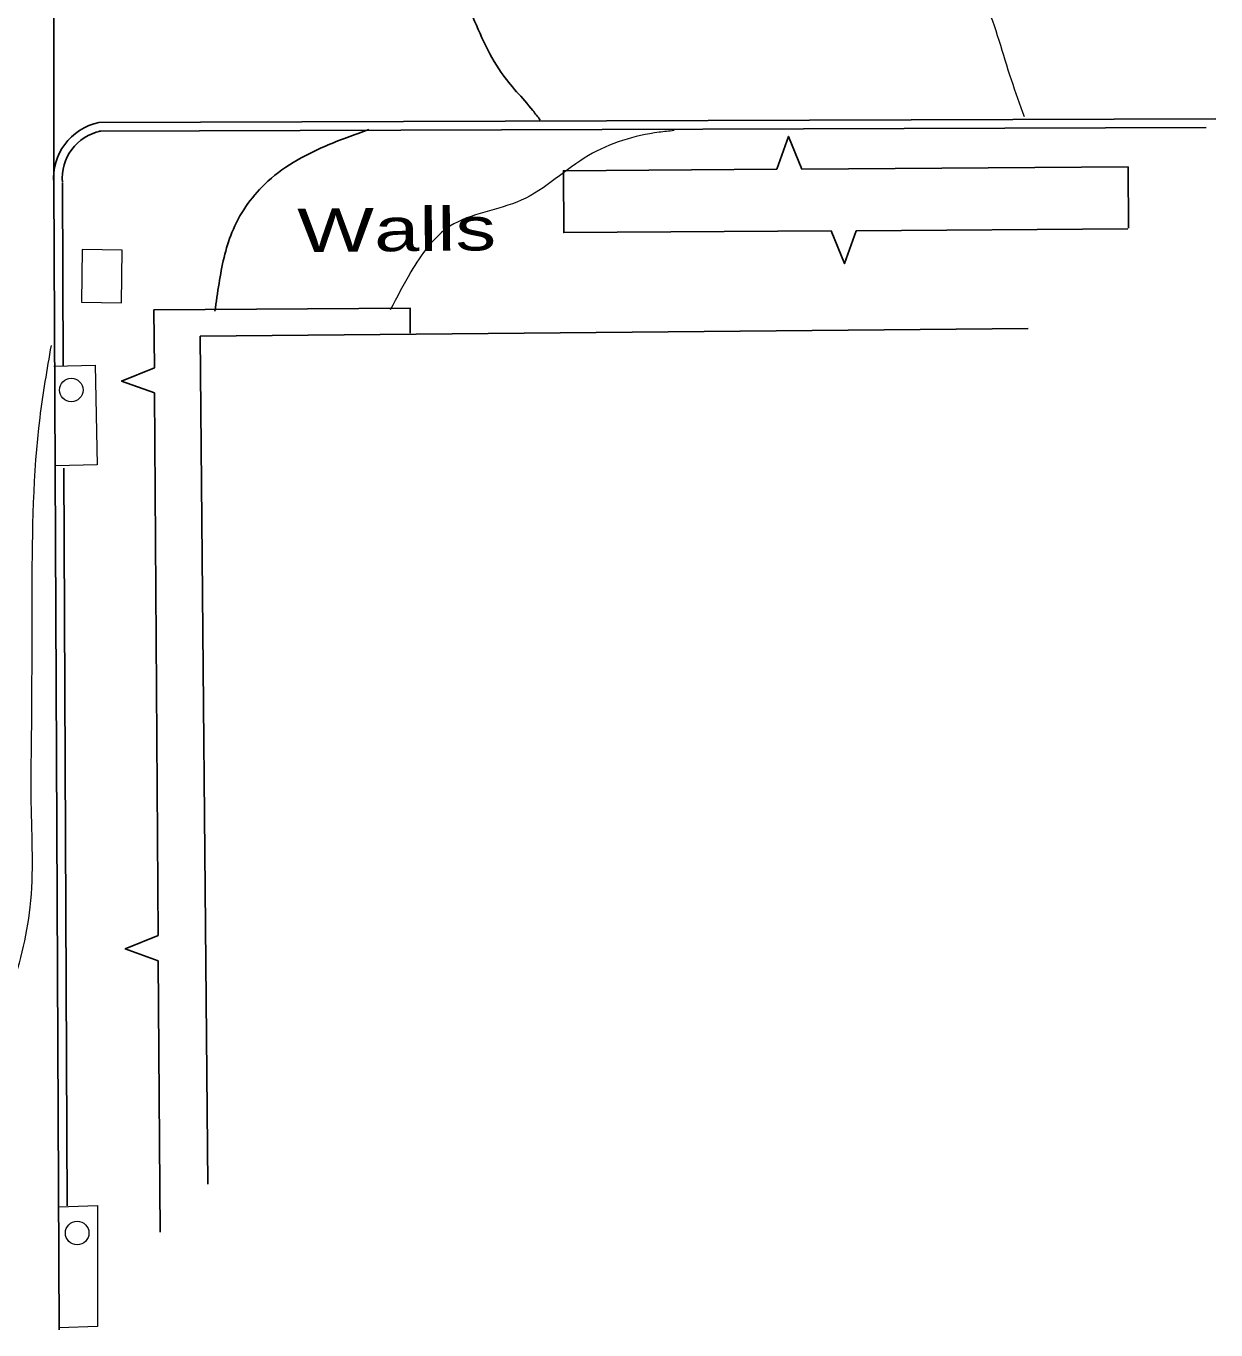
# Model space of a CAD drawing. Extents: x 2361708 to 2370558, y 6977955 to 6991887.
# Drawn here: x 2369161.2 to 2369292.7, y 6989664.3 to 6989808.4 of the extents above; entities that cross this region are included whole.
import ezdxf

# ---------------------------------------------------------------- set-up
doc = ezdxf.new("R2010")
doc.units = 0
doc.header["$LTSCALE"] = 1.9
for name, color, linetype, lineweight in [('11', 7, 'Continuous', 25), ('18', 7, 'Continuous', 25), ('2', 7, 'Continuous', 25), ('31', 7, 'Continuous', 13), ('35', 7, 'Continuous', 13), ('9', 7, 'Continuous', 13)]:
    doc.layers.add(name, color=color, linetype=linetype, lineweight=lineweight)

msp = doc.modelspace()

# ---------------------------------------------------------------- linework, layer by layer
at = {"layer": '11'}
msp.add_lwpolyline([(2369271.974, 6989774.945), (2369180.457, 6989774.103), (2369181.32, 6989680.377)], dxfattribs=at)
at = {"layer": '18'}
for p, q in [((2369282.98, 6989785.97), (2369252.98, 6989785.764)), ((2369175.808, 6989707.856), (2369175.407, 6989767.855)), ((2369176.02, 6989675.086), (2369175.825, 6989705.086))]:
    msp.add_line(p, q, dxfattribs=at)
for points in [[(2369244.185, 6989792.551), (2369245.48, 6989796.193), (2369246.955, 6989792.568)], [(2369246.955, 6989792.568), (2369283.015, 6989792.821), (2369283.059, 6989786.05)], [(2369250.21, 6989785.748), (2369220.641, 6989785.547), (2369220.596, 6989792.386), (2369244.185, 6989792.551)], [(2369252.98, 6989785.764), (2369251.685, 6989782.132), (2369250.21, 6989785.748)], [(2369175.391, 6989770.625), (2369175.35, 6989777.015), (2369203.66, 6989777.204), (2369203.676, 6989774.424)], [(2369175.407, 6989767.855), (2369171.774, 6989769.151), (2369175.391, 6989770.625)], [(2369175.825, 6989705.086), (2369172.182, 6989706.381), (2369175.808, 6989707.856)]]:
    msp.add_lwpolyline(points, dxfattribs=at)
at = {"layer": '2'}
for p, q in [((2369164.281, 6989827.272), (2369164.266, 6989791)), ((2369291.664, 6989797.153), (2369169.262, 6989796.758)), ((2369292.725, 6989798.113), (2369169.263, 6989797.718)), ((2369164.266, 6989791), (2369164.862, 6989664.279)), ((2369165.226, 6989791.009), (2369165.319, 6989770.739)), ((2369165.376, 6989759.509), (2369165.762, 6989677.989))]:
    msp.add_line(p, q, dxfattribs=at)
for radius in [6.311, 5.351]:
    msp.add_arc((2369170.555, 6989791.541), radius, 101.81394, 184.91446, dxfattribs=at)
at = {"layer": '31', "lineweight": 25}
for points in [[(2369209.169, 6989824.579), (2369209.702, 6989823.224), (2369208.413, 6989816.762), (2369210.164, 6989810.328), (2369213.732, 6989803.241), (2369217.212, 6989799.055), (2369218.042, 6989797.993)], [(2369199.111, 6989796.952), (2369194.299, 6989795.116), (2369187.588, 6989790.912), (2369183.969, 6989785.567), (2369182.542, 6989779.944), (2369182.092, 6989776.869)]]:
    msp.add_spline(points, degree=3, dxfattribs=at)
at = {"layer": '35'}
for points in [[(2369236.649, 6989873.053), (2369239.663, 6989865.241), (2369245.698, 6989853.268), (2369252.146, 6989840.799), (2369258.889, 6989826.893), (2369264.935, 6989815.819), (2369267.21, 6989811.101), (2369270.092, 6989802.458), (2369271.521, 6989798.371)], [(2369232.834, 6989796.823), (2369231.176, 6989796.637), (2369223.37, 6989794.063), (2369215.946, 6989789.131), (2369208.063, 6989786.256), (2369203.751, 6989781.206), (2369201.461, 6989777.004)], [(2369135.227, 6989745.572), (2369135.582, 6989731.394), (2369137.878, 6989717.095), (2369140.039, 6989702.375), (2369145.772, 6989690.519), (2369151.714, 6989689.206), (2369155.597, 6989693.123), (2369159.37, 6989701.279), (2369161.677, 6989711.002), (2369161.788, 6989722.553), (2369161.826, 6989730.034), (2369161.892, 6989746.325), (2369162.763, 6989765.094), (2369164.017, 6989773.077)]]:
    msp.add_spline(points, degree=3, dxfattribs=at)
at = {"layer": '9'}
msp.add_lwpolyline([(2369171.752, 6989777.791), (2369171.847, 6989783.622), (2369167.426, 6989783.68), (2369167.341, 6989777.859)], close=True, dxfattribs=at)
for points in [[(2369164.278, 6989770.789), (2369168.838, 6989770.893), (2369169.082, 6989759.884), (2369164.483, 6989759.78)], [(2369164.843, 6989677.88), (2369169.122, 6989678.041), (2369169.109, 6989664.67), (2369164.86, 6989664.509)]]:
    msp.add_lwpolyline(points, dxfattribs=at)
for centre in [(2369166.214, 6989768.158), (2369166.861, 6989674.989)]:
    msp.add_circle(centre, 1.3, dxfattribs=at)

# ---------------------------------------------------------------- texts
at = {"layer": '18', "width": 1.4}
msp.add_text('Walls', height=4.8, rotation=0.545, dxfattribs=at).set_placement((2369191.22, 6989783.396))

doc.saveas('drawing.dxf')
